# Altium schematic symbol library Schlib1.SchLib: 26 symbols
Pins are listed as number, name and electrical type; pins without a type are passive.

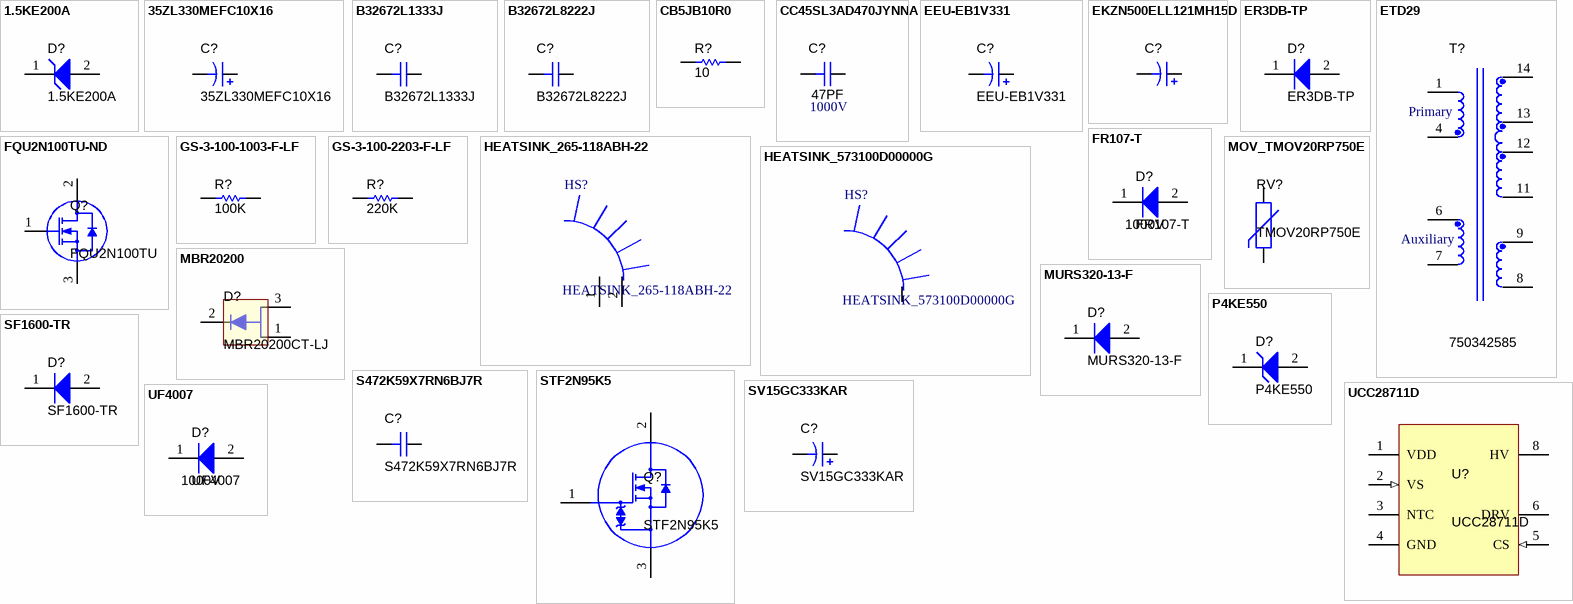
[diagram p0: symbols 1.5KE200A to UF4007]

## 1.5KE200A
designator D?
TVS DIODE 171VWM 274VC AXIAL; Manufacturer: Littelfuse Inc; CompType: Zener
signal-integrity model Diode
footprint Zener_1.5KE200A (TVS DIODE, AXIAL)
pins: 1 K, 2 A

## 35ZL330MEFC10X16
designator C?
CAP ALUM 330UF 35V 20% RADIAL; Manufacturer: Rubycon
footprint R7_1000x1250 (Footprint not found)
pins: 1 +, 2 -

## B32672L1333J
designator C?
CAP FILM 0.033UF 1.6KVDC RADIAL; Manufacturer: EPCOS Inc; Value: 0.033µF; Value1: 1600V (1.6kV)
footprint CAP_18X9_17.5 (CAP FILM 0.033UF 1.6KVDC RADIAL)
pins: 1 +, 2 -

## B32672L8222J
designator C?
CAP FILM 2200PF 2KVDC RADIAL; Manufacturer: EPCOS Inc; Value1: 2000V
pins: 1 +, 2 -

## CB5JB10R0
designator R?  value 10  (hidden comment: CB5JB10R0)
RES 10 OHM 5W 5% CERAMIC WW; Manufacturer: Stackpole Electronics Inc; CompType: Resistor; Tolerance_%: 5; TempCo: ±300ppm/°C; EIA_Code: E96
signal-integrity model Resistor
simulation model Resistor
footprint 0805_HV
footprint 0805
footprint 0805M
footprint 0805L
pins: 1, 2

## CC45SL3AD470JYNNA
designator C?  value 47PF  Value1: 1000V  (hidden comment: CC45SL3AD470JYNNA)
CAP CER 47PF 1KV 5% RADIAL; Manufacturer: TDK Corporation
footprint Radial-CAP_5mmDia _9.5 (Radial, Disc,)
pins: 1 +, 2 -

## EEU-EB1V331
designator C?
CAP ALUM 330UF 35V 20% RADIAL; Manufacturer: Panasonic Electronic Components
pins: 1 +, 2 -

## EKZN500ELL121MH15D
designator C?  (value not drawn)
CAP 120UF 50V RADIAL; Manufacturer: United Chemi-Con
footprint R7_1000x1250 (Footprint not found)
pins: 1 +, 2 -

## ER3DB-TP
designator D?
DIODE SUPER FAST 200V 3A DO214AA; Manufacturer: Micro Commercial Co
signal-integrity model Diode
pins: 1 K, 2 A

## ETD29
designator T?, comment 750342585
Transformer,   TH; Manufacturer: wurth elektronik; SymbolCreator: a0411947; U/M: EA
footprint XFORMER_ETD29
pins: 1, 4, 6, 7, 8, 9, 11, 12, 13, 14

## FQU2N100TU-ND
designator Q?, comment FQU2N100TU
MOSFET N-CH 1000V 1.6A IPAK; Manufacturer: Fairchild Semiconductor; CompType: MOSFET N-Channel
signal-integrity model Diode
pins: 1 G, 2 D, 3 S

## FR107-T
designator D?  value 1000V
DIODE FAST REC 1KV 1A DO41; Manufacturer: Diodes Incorporated
signal-integrity model Diode
pins: 1 K, 2 A

## GS-3-100-1003-F-LF
designator R?  value 100K  (hidden comment: GS-3-100-1003-F-LF)
RES 100K OHM 3W 1% AXIAL; Manufacturer: TT Electronics/IRC; CompType: Resistor; Tolerance_%: 1; Power_W: 5; TempCo: ±100ppm/°C; EIA_Code: E96
signal-integrity model Resistor
simulation model Resistor
footprint RES_570 x 1310 (Thick Film , AXIAL)
pins: 1, 2

## GS-3-100-2203-F-LF
designator R?  value 220K  (hidden comment: GS-3-100-2203-F-LF)
RES 220K OHM 3W 1% AXIAL; Manufacturer: TT Electronics/IRC; CompType: Resistor; Tolerance_%: 1; Power_W: 3; TempCo: ±100ppm/°C
signal-integrity model Resistor
simulation model Resistor
footprint RES_570 x 1310 (Thick Film , AXIAL)
pins: 1, 2

## HEATSINK_265-118ABH-22
designator HS?
Heat Sinks TO-220 VERTICAL MNT; Manufacturer: Wakefield Thermal Solutions; area: 360.000
footprint HEATSINK_265-118ABH-22 (HEATSINK VERT ALUM BLACK TO-220)
pins: 1, 2

## HEATSINK_573100D00000G
designator HS?
TOP MOUNT HEATSINK .4" D-PAK; Manufacturer: Aavid Thermalloy; area: 360.000; Description: TOP MOUNT HEATSINK .4" D-PAK (Horizontal); Mount Orientation: Horizontal
footprint HEATSINK_573100D00000G (TOP MOUNT HEATSINK .4'' D-PAK)
pins: 1

## MBR20200
designator D?, comment MBR20200CT-LJ
DIODE SCHOTTKY 200V 10A TO220AB; Manufacturer: Diodes Incorporated
signal-integrity model Diode
pins: 1 A, 2 K, 3 A

## MOV_TMOV20RP750E
designator RV?, comment TMOV20RP750E
VARISTOR 1080V 10KA DISC 20MM; Manufacturer: Littelfuse Inc
footprint TMOV20RP750E (VARISTOR 1080V 10KA DISC 20MM)
pins: 1, 2

## MURS320-13-F
designator D?
DIODE SUPERFAST 200V 3A SMC; Manufacturer: Diodes Incorporated
signal-integrity model Diode
pins: 1 K, 2 A

## P4KE550
designator D?
TVS DIODE 495VWM 798VC AXIAL; Manufacturer: Littelfuse Inc; CompType: Zener; Value: 495V
signal-integrity model Diode
pins: 1 K, 2 A

## S472K59X7RN6BJ7R
designator C?
CAP CER 4700PF 1KV 10% RADIAL; Manufacturer: Vishay BC Components
pins: 1 +, 2 -

## SF1600-TR
designator D?
DIODE AVALANCHE 1600V 1A SOD57; Manufacturer: Vishay Semiconductor Diodes Division
signal-integrity model Diode
footprint SOD-57
pins: 1 K, 2 A

## STF2N95K5
designator Q?
MOSFET N-CH 950V 2A TO220FP; Manufacturer: STMicroelectronics; CompType: MOSFET N-Channel
signal-integrity model Diode
pins: 1 G, 2 D, 3 S

## SV15GC333KAR
designator C?
CAP CER 0.033UF 2KV 10% RADIAL; Manufacturer: AVX Corporation; Value: 0.033µF; Value1: 2000V
pins: 1 +, 2 -

## UCC28711D
designator U?
IC REG CTRLR FLYBK ISO 7SOIC; Manufacturer: Texas Instruments
pins: 1 VDD, 2 VS (in), 3 NTC, 4 GND, 5 CS (in), 6 DRV, 8 HV

## UF4007
designator D?  value 1000V
DIODE FAST REC 1KV 1A DO41; Manufacturer: Fairchild Semiconductor
signal-integrity model Diode
pins: 1 K, 2 A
